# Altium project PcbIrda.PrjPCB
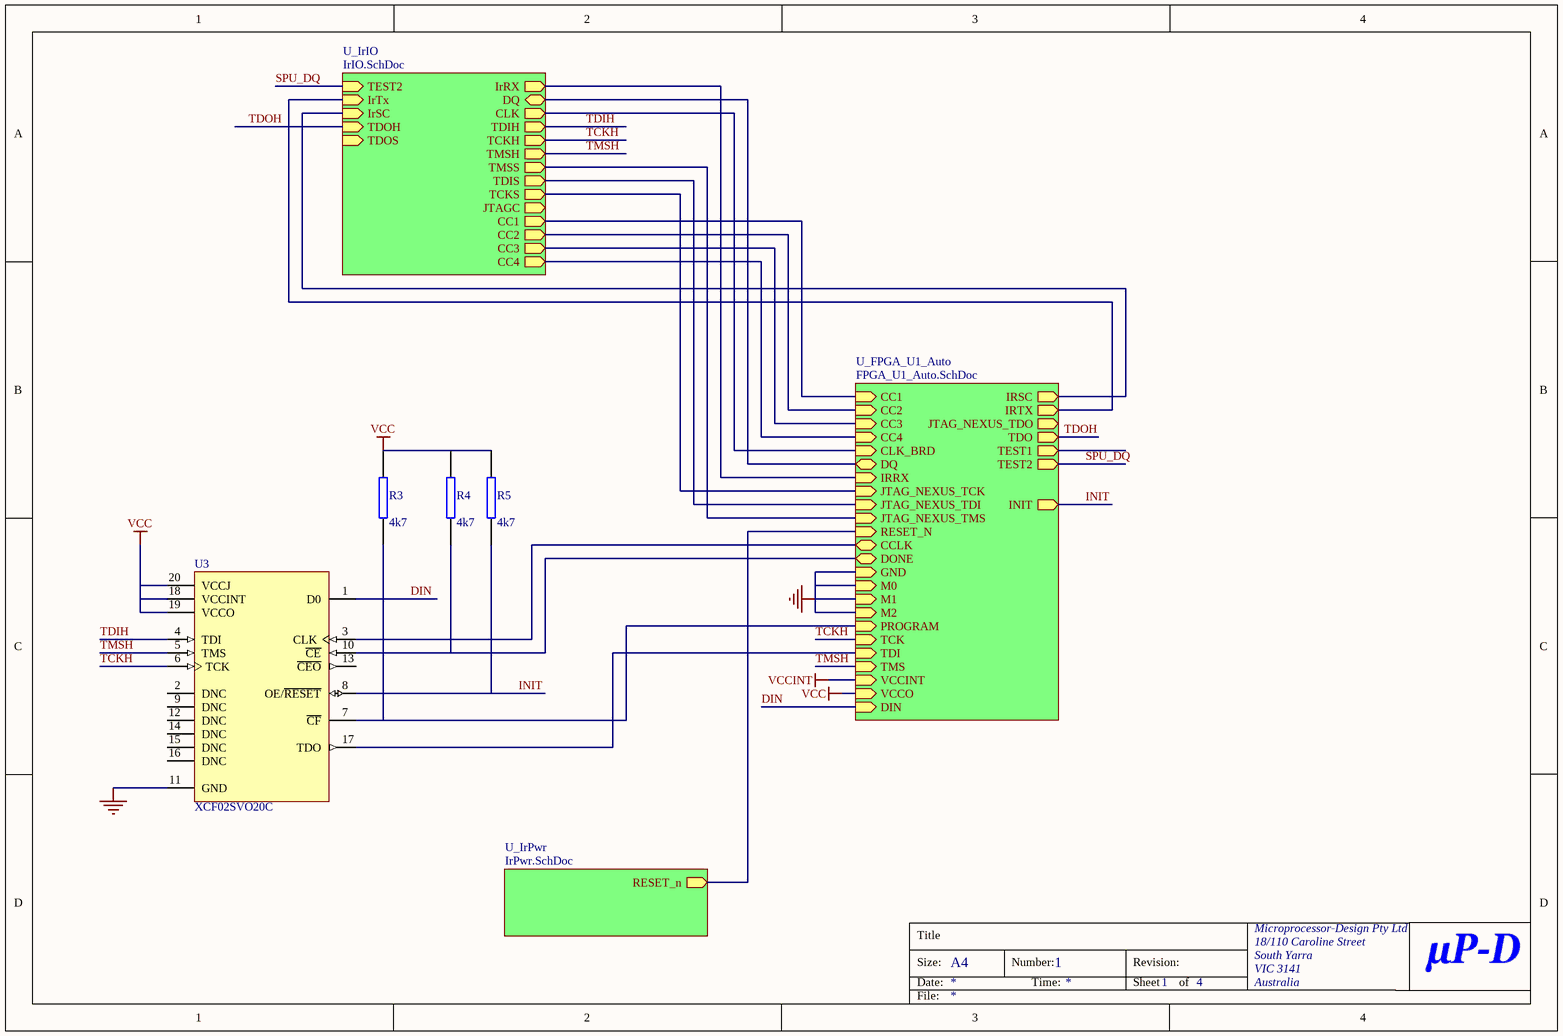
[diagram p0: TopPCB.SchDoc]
4 sheets, 52 parts. Net scope: hierarchical (ports join the sheet entries above them; power ports are global).
Board file: IRDA.PcbDoc
Sheets:
  TopPCB.SchDoc
    U_IrIO = IrIO.SchDoc
    U_IrPwr = IrPwr.SchDoc
    U_FPGA_U1_Auto = FPGA_U1_Auto.SchDoc

## Sheet TopPCB.SchDoc
size A4; Organization: Microprocessor-Design Pty Ltd; Address1: 18/110 Caroline Street; Address2: South Yarra; Address3: VIC 3141; Address4: Australia; DocumentNumber: 1; SheetNumber: 1; SheetTotal: 4

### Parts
R3  4k7  [M0603]
R4  4k7  [M0603]
R5  4k7  [M0603]
U3  XCF02SVO20C  [VO20]

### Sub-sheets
U_FPGA_U1_Auto = FPGA_U1_Auto.SchDoc: CC1 (in), CC2 (in), CC3 (in), CC4 (in), CLK_BRD (in), DIN (in), DQ (bidir), INIT (out), IRRX (in), IRSC (out), IRTX (out), JTAG_NEXUS_TCK (in), JTAG_NEXUS_TDI (in), JTAG_NEXUS_TDO (out), JTAG_NEXUS_TMS (in), RESET_N (in), TEST1 (out), TEST2 (out), CCLK (bidir), DONE (bidir), GND (in), M0 (in), M1 (in), M2 (in), PROGRAM (in), TCK (in), TDI (in), TDO (out), TMS (in), VCCINT (in), VCCO (in)
U_IrIO = IrIO.SchDoc: IrRX (out), DQ (bidir), TEST2 (in), IrTx (in), CLK (out), IrSC (in), TDIH (out), TCKH (out), TDOH (in), TMSH (out), TMSS (out), TDOS (in), TDIS (out), TCKS (out), JTAGC (out), CC1 (out), CC2 (out), CC3 (out), CC4 (out)
U_IrPwr = IrPwr.SchDoc: RESET_n (out)

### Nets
GND: U3.11(GND) ; sheet U_FPGA_U1_Auto/GND, sheet U_FPGA_U1_Auto/M0, sheet U_FPGA_U1_Auto/M1, sheet U_FPGA_U1_Auto/M2
VCC: R3.2 R4.2 R5.2 U3.18(VCCINT) U3.19(VCCO) U3.20(VCCJ) ; sheet U_FPGA_U1_Auto/VCCO  [project net VCCO]
CC1: sheet U_IrIO/CC1, sheet U_FPGA_U1_Auto/CC1
CC2: sheet U_IrIO/CC2, sheet U_FPGA_U1_Auto/CC2
CC3: sheet U_IrIO/CC3, sheet U_FPGA_U1_Auto/CC3
CC4: sheet U_IrIO/CC4, sheet U_FPGA_U1_Auto/CC4
CCLK: U3.3(CLK) ; sheet U_FPGA_U1_Auto/CCLK
CLK_BRD: sheet U_IrIO/CLK, sheet U_FPGA_U1_Auto/CLK_BRD
DIN: U3.1(D0) ; sheet U_FPGA_U1_Auto/DIN
DONE: R4.1 U3.10(~{CE}) ; sheet U_FPGA_U1_Auto/DONE
DQ: sheet U_IrIO/DQ, sheet U_FPGA_U1_Auto/DQ
INIT: R5.1 U3.8(OE/~{RESET}) ; sheet U_FPGA_U1_Auto/INIT
IrRX: sheet U_IrIO/IrRX, sheet U_FPGA_U1_Auto/IRRX
IrSC: sheet U_IrIO/IrSC, sheet U_FPGA_U1_Auto/IRSC
IrTX: sheet U_IrIO/IrTx, sheet U_FPGA_U1_Auto/IRTX
JTAG_NEXUS_TCK: sheet U_IrIO/TCKS, sheet U_FPGA_U1_Auto/JTAG_NEXUS_TCK
JTAG_NEXUS_TDI: sheet U_IrIO/TDIS, sheet U_FPGA_U1_Auto/JTAG_NEXUS_TDI
JTAG_NEXUS_TMS: sheet U_IrIO/TMSS, sheet U_FPGA_U1_Auto/JTAG_NEXUS_TMS
PROGRAM: R3.1 U3.7(~{CF}) ; sheet U_FPGA_U1_Auto/PROGRAM
RESET_n: sheet U_IrPwr/RESET_n, sheet U_FPGA_U1_Auto/RESET_N
SPU_DQ: sheet U_IrIO/TEST2, sheet U_FPGA_U1_Auto/TEST2
TCKH: U3.6(TCK) ; sheet U_IrIO/TCKH, sheet U_FPGA_U1_Auto/TCK  [project net TCK]
TDI: U3.17(TDO) ; sheet U_FPGA_U1_Auto/TDI
TDIH: U3.4(TDI) ; sheet U_IrIO/TDIH
TDOH: sheet U_IrIO/TDOH, sheet U_FPGA_U1_Auto/TDO  [project net TDO]
TMSH: U3.5(TMS) ; sheet U_IrIO/TMSH, sheet U_FPGA_U1_Auto/TMS  [project net TMS]

Not connected (* = marked no-connect by the designer): U3 2(DNC) 9(DNC) 12(DNC) 13(~{CEO}) 14(DNC) 15(DNC) 16(DNC)

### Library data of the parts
R3-R5 = RES: SMT RESISTOR
U3 = XCF02SVO20C: XCF00S Series, Platform Flash In-System Programmable Configuration 3.3V PROM, 20-Pin TSOP, 2-Megabit, Commercial Grade; Manufacturer: Xilinx; Package Information: Latest Revision: ver1.0, May-2003; Code - JEDEC: MO-153-AC

## Sheet IrIO.SchDoc: IrDA - Input/Output
size A4; Organization: Microprocessor-Design Pty Ltd; Address1: 18/110 Caroline Street; Address2: South Yarra; Address3: VIC 3141; Address4: Australia; DocumentNumber: 3; SheetNumber: 3; SheetTotal: 4
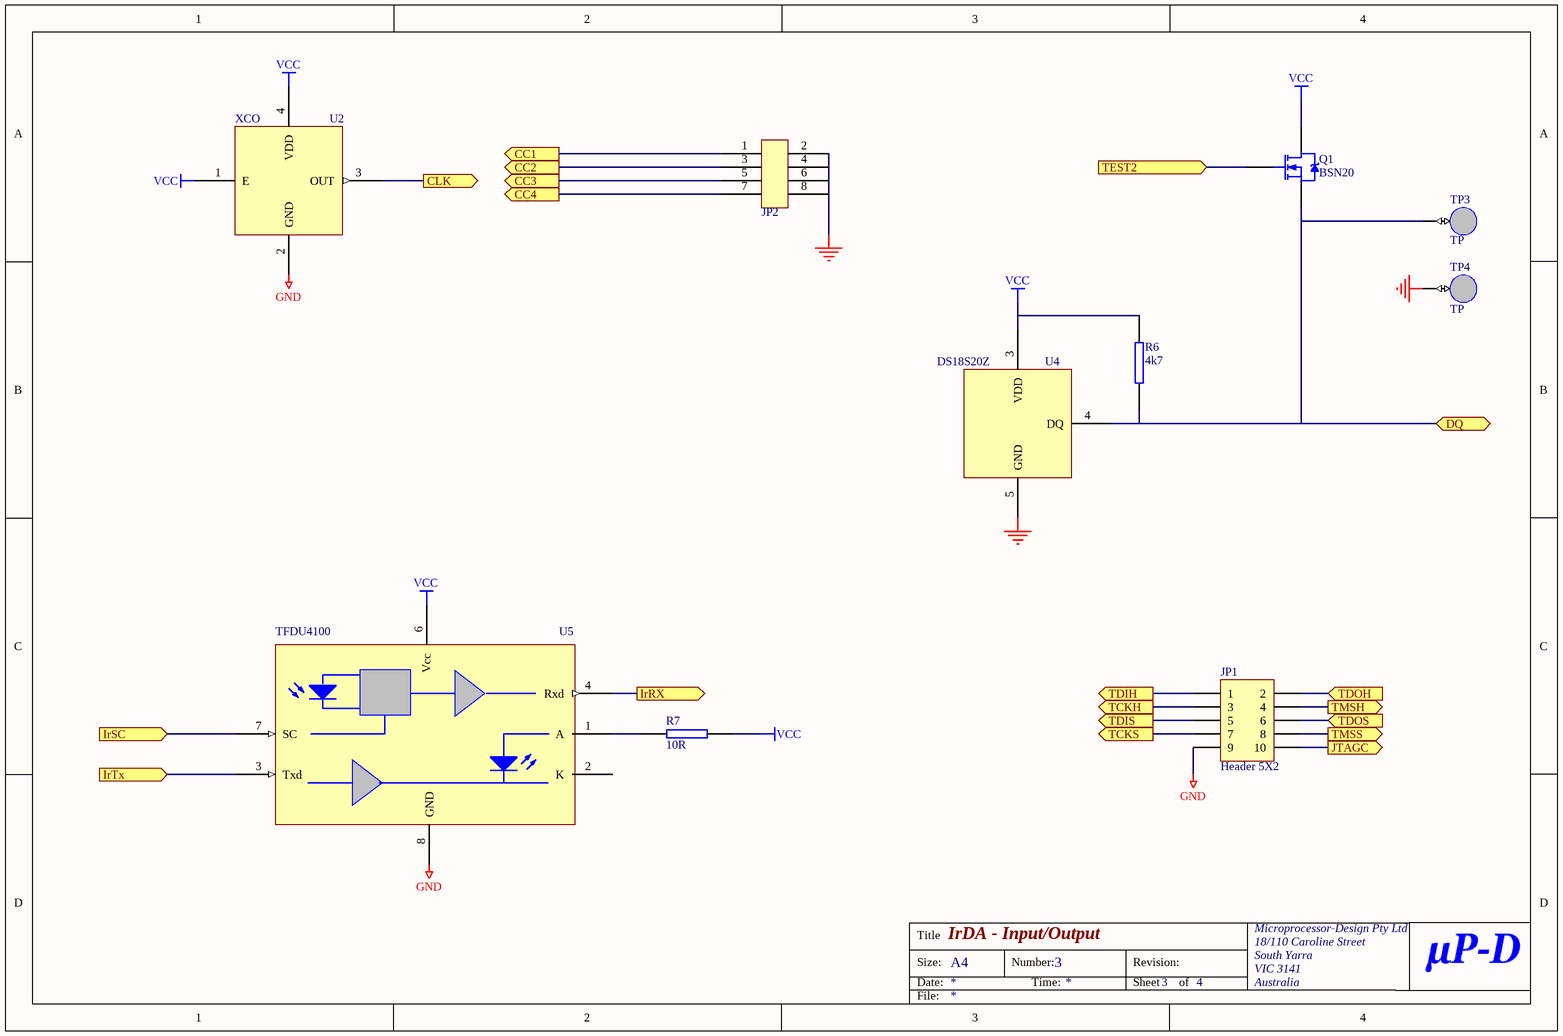
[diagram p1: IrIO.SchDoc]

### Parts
JP1  Header 5X2  [HDR2X5]
JP2  HDR4X2  [HDR4X2]  (value not drawn)
Q1  BSN20  [SOT23]
R6  4k7  [M0603]
R7  10R  [M0603]
TP3  TP  [TP]
TP4  TP  [TP]
U2  XCO  [QSMO-4200]
U4  DS18S20Z  [SO8]
U5  TFDU4100  [TDFU4100]

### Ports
CC1 (out), CC2 (out), CC3 (out), CC4 (out), CLK (out), DQ (bidir), IrRX (out), IrSC (in), IrTx (in), JTAGC (out), TCKH (out), TCKS (out), TDIH (out), TDIS (out), TDOH (in), TDOS (in), TEST2 (in), TMSH (out), TMSS (out)

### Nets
GND: JP1.9 JP2.2 JP2.4 JP2.6 JP2.8 TP4.1(test) U2.2(GND) U4.5(GND) U5.8(GND)
VCC: Q1.2(D) R6.2 R7.2 U2.1(E) U2.4(VDD) U4.3(VDD) U5.6(Vcc)  [project net VCCO]
CC1: JP2.1 ; port CC1
CC2: JP2.3 ; port CC2
CC3: JP2.5 ; port CC3
CC4: JP2.7 ; port CC4
CLK_BRD: U2.3(OUT) ; port CLK
DQ: Q1.3(S) R6.1 TP3.1(test) U4.4(DQ) ; port DQ
IrRX: U5.4(Rxd) ; port IrRX
IrSC: U5.7(SC) ; port IrSC
IrTX: U5.3(Txd) ; port IrTx
JTAG_NEXUS_TCK: JP1.7 ; port TCKS
JTAG_NEXUS_TDI: JP1.5 ; port TDIS
JTAG_NEXUS_TMS: JP1.8 ; port TMSS
SPU_DQ: Q1.1(G) ; port TEST2
TCK: JP1.3 ; port TCKH
TDIH: JP1.1 ; port TDIH
TDO: JP1.2 ; port TDOH
TMS: JP1.4 ; port TMSH
NetJP1_6: JP1.6 ; port TDOS
NetJP1_10: JP1.10 ; port JTAGC
NetR7_1: R7.1 U5.1(A)

Not connected (* = marked no-connect by the designer): U5 2(K)

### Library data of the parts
JP1 = Header 5X2: Header, 5-Pin, Dual row; Manufacturer: Generic Components; Class I: Connector
JP2 = HDR4X2: HEADER 4X2 SQ PIN
Q1 = NMOSFET2
R6 R7 = RES: SMT RESISTOR
TP3 TP4 = TP: SMALL PAD
U5 = TDFU4100: IrDA TxRx; Mfr: Vishay

## Sheet IrPwr.SchDoc: IrDA - Power
size A4; Organization: Microprocessor-Design Pty Ltd; Address1: 18/110 Caroline Street; Address2: South Yarra; Address3: VIC 3141; Address4: Australia; DocumentNumber: 2; SheetNumber: 2; SheetTotal: 4
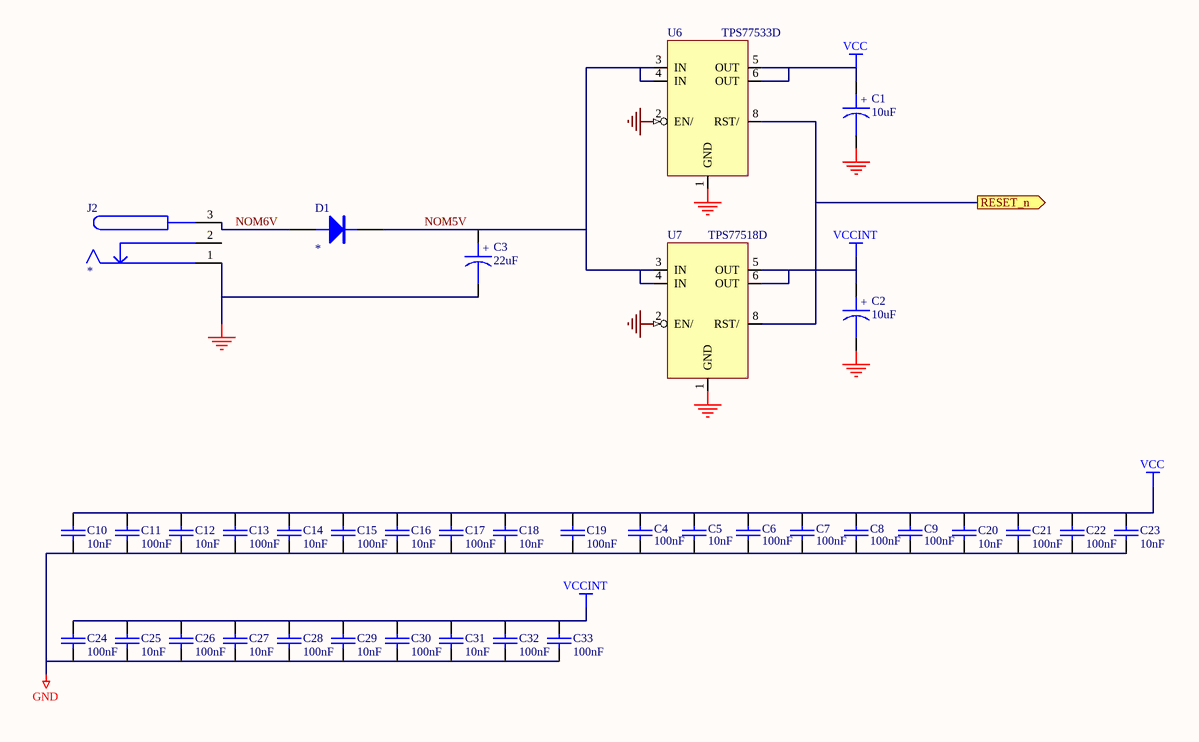
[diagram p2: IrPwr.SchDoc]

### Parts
C1  10uF  [3216POL]
C2  10uF  [3216POL]
C3  22uF  [3216POL]
C4  100nF  [M0603]
C5  10nF  [M0603]
C6  100nF  [M0603]
C7  100nF  [M0603]
C8  100nF  [M0603]
C9  100nF  [M0603]
C10  10nF  [M0603]
C11  100nF  [M0603]
C12  10nF  [M0603]
C13  100nF  [M0603]
C14  10nF  [M0603]
C15  100nF  [M0603]
C16  10nF  [M0603]
C17  100nF  [M0603]
C18  10nF  [M0603]
C19  100nF  [M0603]
C20  10nF  [M0603]
C21  100nF  [M0603]
C22  100nF  [M0603]
C23  10nF  [M0603]
C24  100nF  [M0603]
C25  10nF  [M0603]
C26  100nF  [M0603]
C27  10nF  [M0603]
C28  100nF  [M0603]
C29  10nF  [M0603]
C30  100nF  [M0603]
C31  10nF  [M0603]
C32  100nF  [M0603]
C33  100nF  [M0603]
D1  *  [SOT23]
J2  *  [DC-SOCKET]
U6  TPS77533D  [SO8]
U7  TPS77518D  [SO8]

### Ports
RESET_n (out)

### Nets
GND: C1.2 C2.2 C3.2 C4.2 C5.2 C6.2 C7.2 C8.2 C9.2 C10.2 C11.2 C12.2 C13.2 C14.2 C15.2 C16.2 C17.2 C18.2 C19.2 C20.2 C21.2 C22.2 C23.2 C24.2 C25.2 C26.2 C27.2 C28.2 C29.2 C30.2 C31.2 C32.2 C33.2 J2.1(SHELL) U6.1(GND) U6.2(EN/) U7.1(GND) U7.2(EN/)
VCC: C1.1 C4.1 C5.1 C6.1 C7.1 C8.1 C9.1 C10.1 C11.1 C12.1 C13.1 C14.1 C15.1 C16.1 C17.1 C18.1 C19.1 C20.1 C21.1 C22.1 C23.1 U6.5(OUT) U6.6(OUT)  [project net VCCO]
VCCINT: C2.1 C24.1 C25.1 C26.1 C27.1 C28.1 C29.1 C30.1 C31.1 C32.1 C33.1 U7.5(OUT) U7.6(OUT)
NOM5V: C3.1 D1.2(K) U6.3(IN) U6.4(IN) U7.3(IN) U7.4(IN)
NOM6V: D1.1(A) J2.3(CENTRE)
RESET_n: U6.8(RST/) U7.8(RST/) ; port RESET_n

Not connected (* = marked no-connect by the designer): J2 2(CNTCT)

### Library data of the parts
C1-C3 = CAPACITOR-POL: ELECTROLYTIC/TANTALUM CAP
C4-C33 = CAP: Cap 0603; Text Field1: A TEXT FIELD
D1 = DIODE
J2 = DC-SOCKET: Switchcraft RASM712,Kycon KLD-SMT-0201
U6 U7 = TPS77518D: LDO 1V8 500mA

## Sheet FPGA_U1_Auto.SchDoc
size A3; Organization: Microprocessor-Design Pty Ltd; Address1: 18/110 Caroline Street; Address2: South Yarra; Address3: VIC 3141; Address4: Australia; DocumentNumber: 4; SheetNumber: 4; SheetTotal: 4; Generated From FPGA Project: SoIrDA.PrjFpg; UNUSED_SPECIAL: NoERC; UNUSED_IO: NoERC; VREF: NoERC; UNUSED_INPUT: NoERC
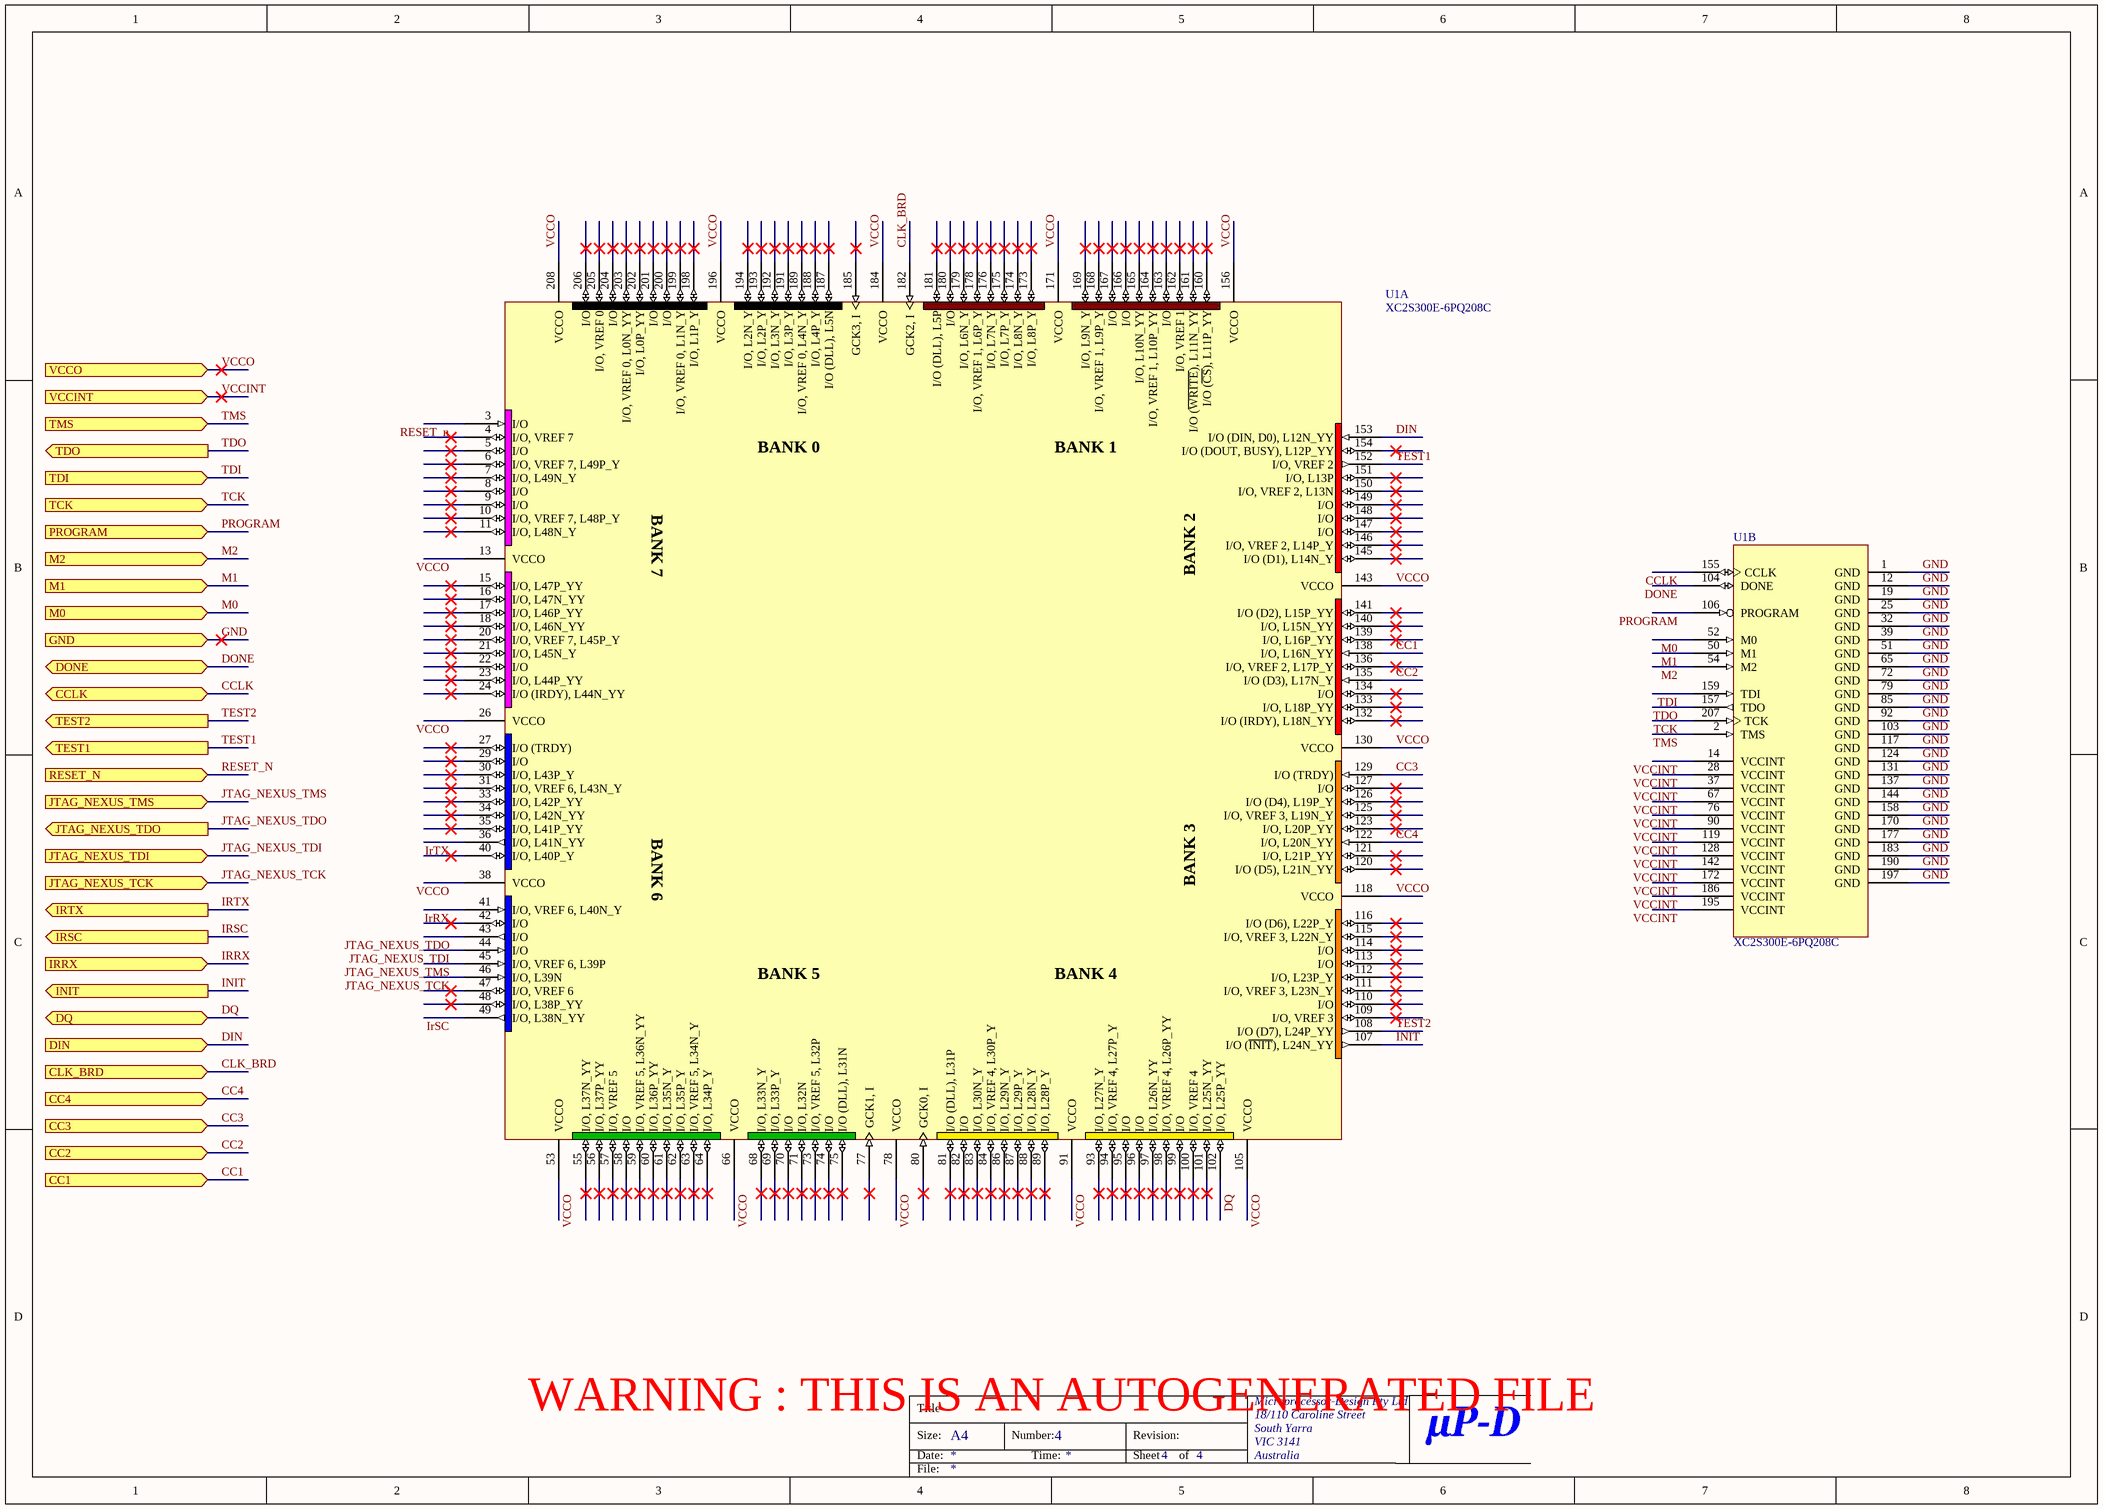
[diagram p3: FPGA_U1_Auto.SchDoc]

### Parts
U1  XC2S300E-6PQ208C  [PQ208]  (parts A,B of 2)

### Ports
CC1 (in), CC2 (in), CC3 (in), CC4 (in), CCLK (bidir), CLK_BRD (in), DIN (in), DONE (bidir), DQ (bidir), GND (in), INIT (out), IRRX (in), IRSC (out), IRTX (out), JTAG_NEXUS_TCK (in), JTAG_NEXUS_TDI (in), JTAG_NEXUS_TDO (out), JTAG_NEXUS_TMS (in), M0 (in), M1 (in), M2 (in), PROGRAM (in), RESET_N (in), TCK (in), TDI (in), TDO (out), TEST1 (out), TEST2 (out), TMS (in), VCCINT (in), VCCO (in)

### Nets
GND: U1.1(GND) U1.12(GND) U1.19(GND) U1.25(GND) U1.32(GND) U1.39(GND) U1.50(M1) U1.51(GND) U1.52(M0) U1.54(M2) U1.65(GND) U1.72(GND) U1.79(GND) U1.85(GND) U1.92(GND) U1.103(GND) U1.117(GND) U1.124(GND) U1.131(GND) U1.137(GND) U1.144(GND) U1.158(GND) U1.170(GND) U1.177(GND) U1.183(GND) U1.190(GND) U1.197(GND) ; port GND, port M0, port M1, port M2  [also labelled M0, M1, M2]
VCCINT: U1.14(VCCINT) U1.28(VCCINT) U1.37(VCCINT) U1.67(VCCINT) U1.76(VCCINT) U1.90(VCCINT) U1.119(VCCINT) U1.128(VCCINT) U1.142(VCCINT) U1.172(VCCINT) U1.186(VCCINT) U1.195(VCCINT) ; port VCCINT
VCCO: U1.13(VCCO) U1.26(VCCO) U1.38(VCCO) U1.53(VCCO) U1.66(VCCO) U1.78(VCCO) U1.91(VCCO) U1.105(VCCO) U1.118(VCCO) U1.130(VCCO) U1.143(VCCO) U1.156(VCCO) U1.171(VCCO) U1.184(VCCO) U1.196(VCCO) U1.208(VCCO) ; port VCCO
CC1: U1.138(I/O,_L16N_YY) ; port CC1
CC2: U1.135(I/O_(D3),_L17N_Y) ; port CC2
CC3: U1.129(I/O_(TRDY)) ; port CC3
CC4: U1.122(I/O,_L20N_YY) ; port CC4
CCLK: U1.155(CCLK) ; port CCLK
CLK_BRD: U1.182(GCK2,_I) ; port CLK_BRD
DIN: U1.153(I/O_(DIN,_D0),_L12N_YY) ; port DIN
DONE: U1.104(DONE) ; port DONE
DQ: U1.102(I/O,_L25P_YY) ; port DQ
INIT: U1.107(I/O_(~{INIT}),_L24N_YY) ; port INIT
IrRX: U1.41(I/O,_VREF_6,_L40N_Y) ; port IRRX
IrSC: U1.49(I/O,_L38N_YY) ; port IRSC
IrTX: U1.36(I/O,_L41N_YY) ; port IRTX
JTAG_NEXUS_TCK: U1.46(I/O,_L39N) ; port JTAG_NEXUS_TCK
JTAG_NEXUS_TDI: U1.44(I/O) ; port JTAG_NEXUS_TDI
JTAG_NEXUS_TDO: U1.43(I/O) ; port JTAG_NEXUS_TDO
JTAG_NEXUS_TMS: U1.45(I/O,_VREF_6,_L39P) ; port JTAG_NEXUS_TMS
PROGRAM: U1.106(PROGRAM) ; port PROGRAM
RESET_n: U1.3(I/O) ; port RESET_N
TCK: U1.207(TCK) ; port TCK
TDI: U1.159(TDI) ; port TDI
TDO: U1.157(TDO) ; port TDO
TEST1: U1.152(I/O,_VREF_2) ; port TEST1
TEST2: U1.108(I/O_(D7),_L24P_YY) ; port TEST2  [project net SPU_DQ]
TMS: U1.2(TMS) ; port TMS

Not connected (* = marked no-connect by the designer): U1 4(I/O,_VREF_7)* 5(I/O)* 6(I/O,_VREF_7,_L49P_Y)* 7(I/O,_L49N_Y)* 8(I/O)* 9(I/O)* 10(I/O,_VREF_7,_L48P_Y)* 11(I/O,_L48N_Y)* 15(I/O,_L47P_YY)* 16(I/O,_L47N_YY)* 17(I/O,_L46P_YY)* 18(I/O,_L46N_YY)* 20(I/O,_VREF_7,_L45P_Y)* 21(I/O,_L45N_Y)* 22(I/O)* 23(I/O,_L44P_YY)* 24(I/O_(IRDY),_L44N_YY)* 27(I/O_(TRDY))* 29(I/O)* 30(I/O,_L43P_Y)* 31(I/O,_VREF_6,_L43N_Y)* 33(I/O,_L42P_YY)* 34(I/O,_L42N_YY)* 35(I/O,_L41P_YY)* 40(I/O,_L40P_Y)* 42(I/O)* 47(I/O,_VREF_6)* 48(I/O,_L38P_YY)* 55(I/O,_L37N_YY)* 56(I/O,_L37P_YY)* 57(I/O,_VREF_5)* 58(I/O)* 59(I/O,_VREF_5,_L36N_YY)* 60(I/O,_L36P_YY)* 61(I/O,_L35N_Y)* 62(I/O,_L35P_Y)* 63(I/O,_VREF_5,_L34N_Y)* 64(I/O,_L34P_Y)* 68(I/O,_L33N_Y)* 69(I/O,_L33P_Y)* 70(I/O)* 71(I/O,_L32N)* 73(I/O,_VREF_5,_L32P)* 74(I/O)* 75(I/O_(DLL),_L31N)* 77(GCK1,_I)* 80(GCK0,_I)* 81(I/O_(DLL),_L31P)* 82(I/O)* 83(I/O,_L30N_Y)* 84(I/O,_VREF_4,_L30P_Y)* 86(I/O,_L29N_Y)* 87(I/O,_L29P_Y)* 88(I/O,_L28N_Y)* 89(I/O,_L28P_Y)* 93(I/O,_L27N_Y)* 94(I/O,_VREF_4,_L27P_Y)* 95(I/O)* 96(I/O)* 97(I/O,_L26N_YY)* 98(I/O,_VREF_4,_L26P_YY)* 99(I/O)* 100(I/O,_VREF_4)* 101(I/O,_L25N_YY)* 109(I/O,_VREF_3)* 110(I/O)* 111(I/O,_VREF_3,_L23N_Y)* 112(I/O,_L23P_Y)* 113(I/O)* 114(I/O)* 115(I/O,_VREF_3,_L22N_Y)* 116(I/O_(D6),_L22P_Y)* 120(I/O_(D5),_L21N_YY)* 121(I/O,_L21P_YY)* 123(I/O,_L20P_YY)* 125(I/O,_VREF_3,_L19N_Y)* 126(I/O_(D4),_L19P_Y)* 127(I/O)* 132(I/O_(IRDY),_L18N_YY)* 133(I/O,_L18P_YY)* 134(I/O)* 136(I/O,_VREF_2,_L17P_Y)* 139(I/O,_L16P_YY)* 140(I/O,_L15N_YY)* 141(I/O_(D2),_L15P_YY)* 145(I/O_(D1),_L14N_Y)* 146(I/O,_VREF_2,_L14P_Y)* 147(I/O)* 148(I/O)* 149(I/O)* 150(I/O,_VREF_2,_L13N)* 151(I/O,_L13P)* 154(I/O_(DOUT,_BUSY),_L12P_YY)* 160(I/O_(~{CS}),_L11P_YY)* 161(I/O_(~{WRITE}),_L11N_YY)* 162(I/O,_VREF_1)* 163(I/O)* 164(I/O,_VREF_1,_L10P_YY)* 165(I/O,_L10N_YY)* 166(I/O)* 167(I/O)* 168(I/O,_VREF_1,_L9P_Y)* 169(I/O,_L9N_Y)* 173(I/O,_L8P_Y)* 174(I/O,_L8N_Y)* 175(I/O,_L7P_Y)* 176(I/O,_L7N_Y)* 178(I/O,_VREF_1,_L6P_Y)* 179(I/O,_L6N_Y)* 180(I/O)* 181(I/O_(DLL),_L5P)* 185(GCK3,_I)* 187(I/O_(DLL),_L5N)* 188(I/O,_L4P_Y)* 189(I/O,_VREF_0,_L4N_Y)* 191(I/O,_L3P_Y)* 192(I/O,_L3N_Y)* 193(I/O,_L2P_Y)* 194(I/O,_L2N_Y)* 198(I/O,_L1P_Y)* 199(I/O,_VREF_0,_L1N_Y)* 200(I/O)* 201(I/O)* 202(I/O,_L0P_YY)* 203(I/O,_VREF_0,_L0N_YY)* 204(I/O)* 205(I/O,_VREF_0)* 206(I/O)*

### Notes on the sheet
- WARNING : THIS IS AN AUTOGENERATED FILE

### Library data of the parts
U1 = XC2S300E-6PQ208C: Spartan-IIE 1.8V FPGA, 208-Pin PQFP, Standard Performance, Commercial Grade; Package Information: Latest Revision: ver1.1, Oct-2002; Code - JEDEC: MS-029-FA-1

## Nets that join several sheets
GND: TopPCB (U3.11), IrIO (9 pins), IrPwr (38 pins), FPGA_U1_Auto (27 pins)
VCCINT: IrPwr (13 pins), FPGA_U1_Auto (12 pins)
VCCO: TopPCB (6 pins), IrIO (7 pins), IrPwr (23 pins), FPGA_U1_Auto (16 pins)
CC1: IrIO (JP2.1), FPGA_U1_Auto (U1.138)
CC2: IrIO (JP2.3), FPGA_U1_Auto (U1.135)
CC3: IrIO (JP2.5), FPGA_U1_Auto (U1.129)
CC4: IrIO (JP2.7), FPGA_U1_Auto (U1.122)
CCLK: TopPCB (U3.3), FPGA_U1_Auto (U1.155)
CLK_BRD: IrIO (U2.3), FPGA_U1_Auto (U1.182)
DIN: TopPCB (U3.1), FPGA_U1_Auto (U1.153)
DONE: TopPCB (R4.1 U3.10), FPGA_U1_Auto (U1.104)
DQ: IrIO (Q1.3 R6.1 TP3.1 U4.4), FPGA_U1_Auto (U1.102)
INIT: TopPCB (R5.1 U3.8), FPGA_U1_Auto (U1.107)
IrRX: IrIO (U5.4), FPGA_U1_Auto (U1.41)
IrSC: IrIO (U5.7), FPGA_U1_Auto (U1.49)
IrTX: IrIO (U5.3), FPGA_U1_Auto (U1.36)
JTAG_NEXUS_TCK: IrIO (JP1.7), FPGA_U1_Auto (U1.46)
JTAG_NEXUS_TDI: IrIO (JP1.5), FPGA_U1_Auto (U1.44)
JTAG_NEXUS_TMS: IrIO (JP1.8), FPGA_U1_Auto (U1.45)
PROGRAM: TopPCB (R3.1 U3.7), FPGA_U1_Auto (U1.106)
RESET_n: IrPwr (U6.8 U7.8), FPGA_U1_Auto (U1.3)
SPU_DQ: IrIO (Q1.1), FPGA_U1_Auto (U1.108)
TCK: TopPCB (U3.6), IrIO (JP1.3), FPGA_U1_Auto (U1.207)
TDI: TopPCB (U3.17), FPGA_U1_Auto (U1.159)
TDIH: TopPCB (U3.4), IrIO (JP1.1)
TDO: IrIO (JP1.2), FPGA_U1_Auto (U1.157)
TMS: TopPCB (U3.5), IrIO (JP1.4), FPGA_U1_Auto (U1.2)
